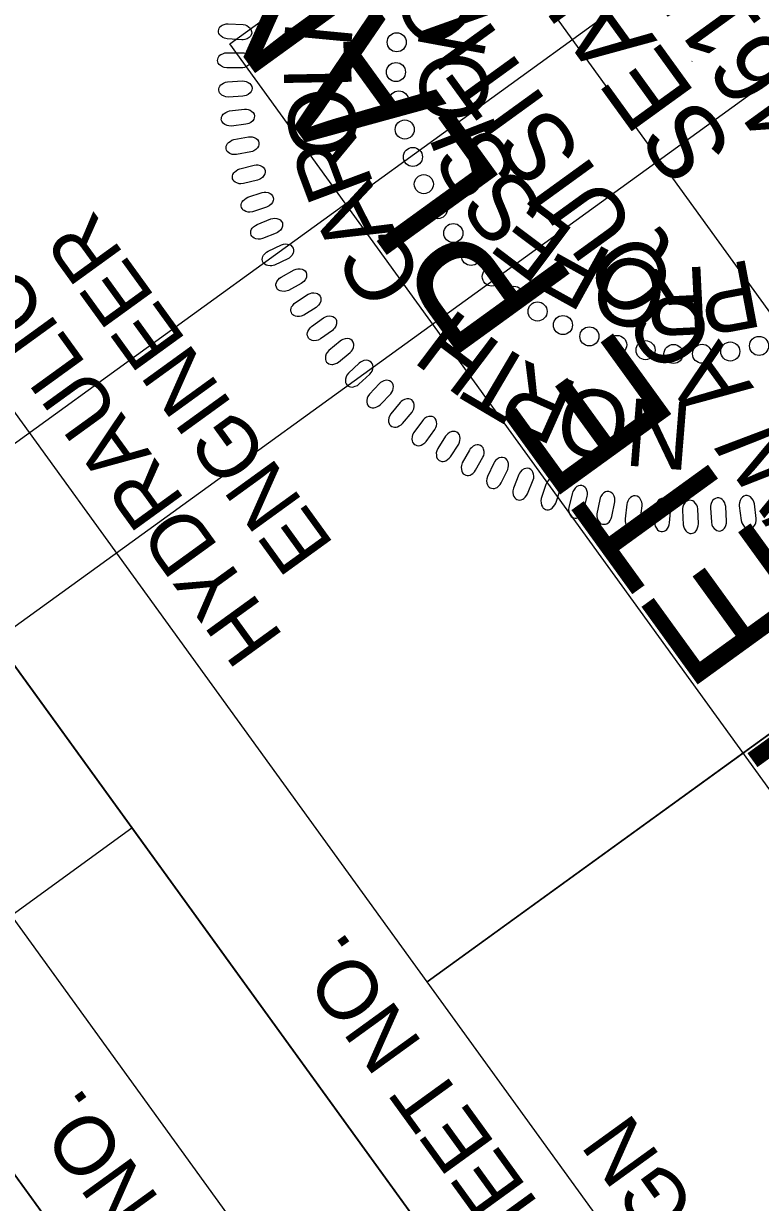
# Model space of a CAD drawing. Extents: x 474925 to 478950, y 494687 to 502905.
# Drawn here: x 475008.2 to 475070.1, y 502185.1 to 502284.1 of the extents above; entities that cross this region are included whole.
import ezdxf

# ---------------------------------------------------------------- set-up
doc = ezdxf.new("R2010")
doc.units = 0
for name, color, linetype in [('Sheet PE Seal Cell', 7, 'Continuous'), ('Sheet Plan CELL', 7, 'Continuous'), ('Sheet Plan Layout CELL', 7, 'Continuous'), ('Sheet Plot Border Inside CELL', 7, 'Continuous'), ('Sheet Sticker Incomplete CELL', 7, 'Continuous')]:
    doc.layers.add(name, color=color, linetype=linetype)

msp = doc.modelspace()

# ---------------------------------------------------------------- linework, layer by layer
at = {"layer": 'Sheet PE Seal Cell'}
msp.add_line((475064.349, 502280.924), (475064.387, 502280.952), dxfattribs=at)
for points in [[(475026.565, 502282.734), (475025.341, 502282.813), (475025.124, 502282.864), (475024.988, 502282.926), (475024.826, 502283.049), (475024.723, 502283.152), (475024.651, 502283.27), (475024.618, 502283.376), (475024.605, 502283.49), (475024.632, 502283.6), (475024.67, 502283.718), (475024.736, 502283.819), (475024.842, 502283.916), (475024.926, 502283.971), (475025.08, 502284.028), (475025.263, 502284.077), (475025.423, 502284.089), (475026.677, 502284.015), (475026.846, 502283.982), (475026.982, 502283.927), (475027.135, 502283.828), (475027.268, 502283.707), (475027.341, 502283.605), (475027.391, 502283.444), (475027.4, 502283.294), (475027.351, 502283.147), (475027.295, 502283.046), (475027.187, 502282.926), (475027.01, 502282.818), (475026.826, 502282.762), (475026.695, 502282.741)], [(475026.529, 502280.369), (475025.302, 502280.371), (475025.082, 502280.409), (475024.943, 502280.461), (475024.774, 502280.574), (475024.664, 502280.671), (475024.585, 502280.783), (475024.545, 502280.889), (475024.525, 502281.001), (475024.545, 502281.112), (475024.575, 502281.232), (475024.635, 502281.336), (475024.735, 502281.441), (475024.815, 502281.501), (475024.965, 502281.568), (475025.144, 502281.627), (475025.304, 502281.649), (475026.561, 502281.654), (475026.73, 502281.631), (475026.87, 502281.586), (475027.029, 502281.497), (475027.169, 502281.384), (475027.248, 502281.286), (475027.308, 502281.129), (475027.327, 502280.98), (475027.288, 502280.83), (475027.237, 502280.726), (475027.138, 502280.599), (475026.967, 502280.48), (475026.788, 502280.413), (475026.658, 502280.383)], [(475026.67, 502278.002), (475025.446, 502277.928), (475025.225, 502277.951), (475025.082, 502277.995), (475024.906, 502278.097), (475024.79, 502278.187), (475024.704, 502278.294), (475024.658, 502278.396), (475024.631, 502278.507), (475024.644, 502278.62), (475024.667, 502278.741), (475024.72, 502278.849), (475024.813, 502278.96), (475024.89, 502279.024), (475025.035, 502279.101), (475025.21, 502279.171), (475025.368, 502279.203), (475026.622, 502279.287), (475026.792, 502279.275), (475026.934, 502279.239), (475027.099, 502279.159), (475027.245, 502279.056), (475027.332, 502278.964), (475027.401, 502278.81), (475027.429, 502278.662), (475027.399, 502278.511), (475027.355, 502278.403), (475027.264, 502278.27), (475027.102, 502278.141), (475026.926, 502278.063), (475026.799, 502278.025)], [(475026.917, 502275.64), (475025.7, 502275.489), (475025.478, 502275.499), (475025.333, 502275.533), (475025.151, 502275.624), (475025.03, 502275.707), (475024.937, 502275.808), (475024.884, 502275.907), (475024.851, 502276.016), (475024.857, 502276.13), (475024.872, 502276.252), (475024.918, 502276.363), (475025.004, 502276.479), (475025.076, 502276.548), (475025.216, 502276.634), (475025.387, 502276.715), (475025.542, 502276.758), (475026.789, 502276.92), (475026.959, 502276.918), (475027.104, 502276.891), (475027.273, 502276.822), (475027.426, 502276.728), (475027.517, 502276.641), (475027.596, 502276.493), (475027.634, 502276.347), (475027.613, 502276.194), (475027.576, 502276.083), (475027.492, 502275.945), (475027.339, 502275.806), (475027.169, 502275.717), (475027.044, 502275.671)], [(475027.341, 502273.324), (475026.135, 502273.097), (475025.913, 502273.093), (475025.766, 502273.118), (475025.578, 502273.197), (475025.453, 502273.272), (475025.354, 502273.368), (475025.295, 502273.463), (475025.254, 502273.57), (475025.254, 502273.684), (475025.26, 502273.807), (475025.3, 502273.921), (475025.379, 502274.042), (475025.446, 502274.115), (475025.581, 502274.209), (475025.746, 502274.301), (475025.898, 502274.353), (475027.132, 502274.594), (475027.302, 502274.603), (475027.448, 502274.585), (475027.622, 502274.526), (475027.78, 502274.442), (475027.876, 502274.361), (475027.964, 502274.218), (475028.011, 502274.074), (475028, 502273.921), (475027.97, 502273.809), (475027.896, 502273.665), (475027.751, 502273.516), (475027.587, 502273.417), (475027.466, 502273.364)], [(475027.899, 502270.961), (475026.71, 502270.659), (475026.488, 502270.641), (475026.34, 502270.656), (475026.148, 502270.724), (475026.017, 502270.791), (475025.913, 502270.88), (475025.848, 502270.971), (475025.801, 502271.075), (475025.793, 502271.188), (475025.792, 502271.312), (475025.825, 502271.428), (475025.895, 502271.554), (475025.958, 502271.632), (475026.086, 502271.734), (475026.245, 502271.836), (475026.394, 502271.897), (475027.61, 502272.215), (475027.78, 502272.234), (475027.927, 502272.226), (475028.103, 502272.178), (475028.267, 502272.104), (475028.368, 502272.03), (475028.464, 502271.892), (475028.52, 502271.752), (475028.519, 502271.598), (475028.496, 502271.484), (475028.431, 502271.336), (475028.296, 502271.178), (475028.139, 502271.068), (475028.02, 502271.008)], [(475028.643, 502268.681), (475027.475, 502268.304), (475027.254, 502268.272), (475027.106, 502268.279), (475026.91, 502268.334), (475026.776, 502268.393), (475026.665, 502268.474), (475026.596, 502268.562), (475026.542, 502268.663), (475026.527, 502268.775), (475026.519, 502268.899), (475026.543, 502269.017), (475026.606, 502269.146), (475026.663, 502269.228), (475026.785, 502269.338), (475026.938, 502269.45), (475027.082, 502269.521), (475028.276, 502269.913), (475028.444, 502269.945), (475028.591, 502269.945), (475028.771, 502269.909), (475028.938, 502269.844), (475029.043, 502269.777), (475029.149, 502269.645), (475029.213, 502269.509), (475029.221, 502269.355), (475029.206, 502269.24), (475029.15, 502269.088), (475029.026, 502268.923), (475028.876, 502268.803), (475028.761, 502268.735)], [(475029.458, 502266.494), (475028.317, 502266.044), (475028.1, 502265.999), (475027.95, 502265.996), (475027.751, 502266.038), (475027.614, 502266.088), (475027.498, 502266.164), (475027.423, 502266.246), (475027.363, 502266.344), (475027.34, 502266.455), (475027.324, 502266.577), (475027.342, 502266.697), (475027.396, 502266.83), (475027.448, 502266.915), (475027.563, 502267.033), (475027.708, 502267.154), (475027.849, 502267.234), (475029.015, 502267.701), (475029.181, 502267.742), (475029.328, 502267.751), (475029.509, 502267.726), (475029.68, 502267.673), (475029.79, 502267.612), (475029.903, 502267.488), (475029.976, 502267.356), (475029.993, 502267.202), (475029.986, 502267.087), (475029.939, 502266.932), (475029.826, 502266.758), (475029.683, 502266.63), (475029.574, 502266.555)], [(475030.426, 502264.348), (475029.316, 502263.829), (475029.101, 502263.769), (475028.953, 502263.758), (475028.751, 502263.787), (475028.611, 502263.829), (475028.491, 502263.896), (475028.411, 502263.974), (475028.345, 502264.067), (475028.315, 502264.177), (475028.292, 502264.298), (475028.302, 502264.419), (475028.348, 502264.556), (475028.394, 502264.643), (475028.501, 502264.768), (475028.638, 502264.898), (475028.774, 502264.987), (475029.909, 502265.526), (475030.072, 502265.577), (475030.217, 502265.596), (475030.4, 502265.582), (475030.574, 502265.54), (475030.687, 502265.486), (475030.808, 502265.369), (475030.889, 502265.242), (475030.917, 502265.09), (475030.916, 502264.974), (475030.879, 502264.817), (475030.776, 502264.636), (475030.643, 502264.499), (475030.537, 502264.417)], [(475031.566, 502262.286), (475030.49, 502261.697), (475030.28, 502261.624), (475030.133, 502261.603), (475029.93, 502261.62), (475029.787, 502261.653), (475029.663, 502261.713), (475029.578, 502261.785), (475029.507, 502261.874), (475029.47, 502261.983), (475029.439, 502262.101), (475029.441, 502262.222), (475029.479, 502262.362), (475029.52, 502262.452), (475029.619, 502262.584), (475029.748, 502262.722), (475029.877, 502262.818), (475030.976, 502263.428), (475031.135, 502263.49), (475031.279, 502263.517), (475031.462, 502263.515), (475031.638, 502263.484), (475031.755, 502263.437), (475031.883, 502263.328), (475031.972, 502263.207), (475032.009, 502263.056), (475032.016, 502262.941), (475031.989, 502262.781), (475031.898, 502262.594), (475031.772, 502262.45), (475031.673, 502262.361)], [(475032.81, 502260.27), (475031.773, 502259.614), (475031.568, 502259.528), (475031.422, 502259.498), (475031.218, 502259.503), (475031.074, 502259.526), (475030.946, 502259.578), (475030.857, 502259.646), (475030.78, 502259.73), (475030.737, 502259.835), (475030.699, 502259.952), (475030.693, 502260.073), (475030.721, 502260.214), (475030.757, 502260.307), (475030.847, 502260.444), (475030.967, 502260.591), (475031.09, 502260.695), (475032.149, 502261.372), (475032.304, 502261.444), (475032.446, 502261.481), (475032.629, 502261.49), (475032.806, 502261.47), (475032.926, 502261.431), (475033.061, 502261.33), (475033.158, 502261.214), (475033.204, 502261.066), (475033.217, 502260.951), (475033.201, 502260.79), (475033.121, 502260.599), (475033.006, 502260.446), (475032.911, 502260.351)], [(475034.172, 502258.343), (475033.179, 502257.624), (475032.979, 502257.526), (475032.834, 502257.486), (475032.632, 502257.478), (475032.486, 502257.492), (475032.356, 502257.536), (475032.262, 502257.597), (475032.18, 502257.677), (475032.131, 502257.779), (475032.085, 502257.894), (475032.072, 502258.013), (475032.091, 502258.157), (475032.121, 502258.252), (475032.203, 502258.394), (475032.313, 502258.548), (475032.429, 502258.66), (475033.443, 502259.402), (475033.593, 502259.484), (475033.733, 502259.529), (475033.914, 502259.55), (475034.094, 502259.541), (475034.215, 502259.509), (475034.356, 502259.417), (475034.459, 502259.307), (475034.515, 502259.163), (475034.535, 502259.049), (475034.53, 502258.888), (475034.462, 502258.691), (475034.356, 502258.531), (475034.268, 502258.431)], [(475034.834, 502257.445), (475033.887, 502256.665), (475033.741, 502256.496), (475033.667, 502256.368), (475033.607, 502256.173), (475033.584, 502256.028), (475033.594, 502255.891), (475033.63, 502255.785), (475033.686, 502255.686), (475033.773, 502255.612), (475033.872, 502255.539), (475033.984, 502255.496), (475034.128, 502255.479), (475034.227, 502255.483), (475034.386, 502255.526), (475034.563, 502255.594), (475034.7, 502255.678), (475035.674, 502256.472), (475035.791, 502256.597), (475035.87, 502256.72), (475035.937, 502256.891), (475035.972, 502257.067), (475035.973, 502257.192), (475035.919, 502257.352), (475035.839, 502257.48), (475035.713, 502257.57), (475035.608, 502257.619), (475035.45, 502257.653), (475035.244, 502257.638), (475035.062, 502257.575), (475034.943, 502257.516)], [(475036.428, 502255.589), (475035.532, 502254.751), (475035.397, 502254.574), (475035.331, 502254.44), (475035.284, 502254.243), (475035.27, 502254.097), (475035.288, 502253.961), (475035.331, 502253.856), (475035.393, 502253.761), (475035.484, 502253.693), (475035.588, 502253.626), (475035.703, 502253.59), (475035.847, 502253.582), (475035.946, 502253.593), (475036.101, 502253.646), (475036.273, 502253.725), (475036.405, 502253.817), (475037.328, 502254.67), (475037.436, 502254.803), (475037.508, 502254.931), (475037.563, 502255.105), (475037.588, 502255.282), (475037.58, 502255.408), (475037.517, 502255.564), (475037.429, 502255.687), (475037.298, 502255.768), (475037.19, 502255.811), (475037.03, 502255.835), (475036.825, 502255.807), (475036.648, 502255.733), (475036.533, 502255.666)], [(475038.122, 502253.876), (475037.281, 502252.984), (475037.158, 502252.799), (475037.1, 502252.661), (475037.065, 502252.461), (475037.061, 502252.315), (475037.087, 502252.179), (475037.136, 502252.079), (475037.204, 502251.987), (475037.299, 502251.924), (475037.407, 502251.865), (475037.524, 502251.836), (475037.669, 502251.837), (475037.767, 502251.854), (475037.919, 502251.917), (475038.085, 502252.006), (475038.211, 502252.107), (475039.078, 502253.016), (475039.179, 502253.155), (475039.242, 502253.287), (475039.286, 502253.465), (475039.3, 502253.644), (475039.284, 502253.768), (475039.211, 502253.919), (475039.116, 502254.036), (475038.979, 502254.11), (475038.869, 502254.145), (475038.708, 502254.16), (475038.505, 502254.119), (475038.333, 502254.034), (475038.223, 502253.96)], [(475039.857, 502252.286), (475039.073, 502251.342), (475038.962, 502251.15), (475038.912, 502251.009), (475038.891, 502250.807), (475038.895, 502250.66), (475038.931, 502250.527), (475038.985, 502250.429), (475039.059, 502250.343), (475039.158, 502250.286), (475039.269, 502250.233), (475039.388, 502250.212), (475039.532, 502250.222), (475039.629, 502250.245), (475039.777, 502250.317), (475039.937, 502250.417), (475040.056, 502250.525), (475040.865, 502251.487), (475040.956, 502251.632), (475041.011, 502251.768), (475041.044, 502251.948), (475041.047, 502252.127), (475041.023, 502252.25), (475040.94, 502252.398), (475040.838, 502252.508), (475040.698, 502252.573), (475040.585, 502252.602), (475040.424, 502252.606), (475040.224, 502252.552), (475040.057, 502252.457), (475039.952, 502252.376)], [(475041.728, 502250.76), (475041.005, 502249.769), (475040.906, 502249.57), (475040.866, 502249.426), (475040.856, 502249.223), (475040.87, 502249.077), (475040.914, 502248.947), (475040.975, 502248.852), (475041.054, 502248.77), (475041.156, 502248.72), (475041.27, 502248.674), (475041.39, 502248.661), (475041.533, 502248.679), (475041.629, 502248.709), (475041.772, 502248.79), (475041.926, 502248.9), (475042.038, 502249.015), (475042.785, 502250.026), (475042.866, 502250.176), (475042.912, 502250.316), (475042.934, 502250.497), (475042.926, 502250.676), (475042.894, 502250.798), (475042.802, 502250.939), (475042.693, 502251.043), (475042.549, 502251.099), (475042.435, 502251.12), (475042.274, 502251.115), (475042.077, 502251.048), (475041.917, 502250.943), (475041.816, 502250.856)], [(475043.68, 502249.456), (475043.021, 502248.421), (475042.935, 502248.216), (475042.903, 502248.071), (475042.907, 502247.867), (475042.93, 502247.723), (475042.982, 502247.595), (475043.048, 502247.505), (475043.133, 502247.428), (475043.238, 502247.385), (475043.355, 502247.346), (475043.475, 502247.34), (475043.617, 502247.367), (475043.71, 502247.403), (475043.847, 502247.493), (475043.994, 502247.612), (475044.099, 502247.734), (475044.78, 502248.79), (475044.852, 502248.945), (475044.89, 502249.087), (475044.9, 502249.27), (475044.881, 502249.448), (475044.842, 502249.567), (475044.741, 502249.702), (475044.625, 502249.799), (475044.478, 502249.845), (475044.363, 502249.86), (475044.202, 502249.844), (475044.01, 502249.766), (475043.857, 502249.65), (475043.762, 502249.557)], [(475045.678, 502248.288), (475045.084, 502247.214), (475045.011, 502247.004), (475044.99, 502246.856), (475045.005, 502246.654), (475045.038, 502246.511), (475045.097, 502246.387), (475045.17, 502246.301), (475045.258, 502246.23), (475045.366, 502246.193), (475045.485, 502246.161), (475045.605, 502246.163), (475045.745, 502246.2), (475045.836, 502246.241), (475045.967, 502246.339), (475046.107, 502246.467), (475046.203, 502246.596), (475046.817, 502247.692), (475046.88, 502247.852), (475046.908, 502247.996), (475046.906, 502248.179), (475046.876, 502248.356), (475046.829, 502248.472), (475046.721, 502248.6), (475046.6, 502248.69), (475046.449, 502248.727), (475046.334, 502248.734), (475046.174, 502248.709), (475045.988, 502248.618), (475045.842, 502248.493), (475045.753, 502248.394)], [(475047.721, 502247.196), (475047.196, 502246.086), (475047.136, 502245.872), (475047.123, 502245.724), (475047.152, 502245.522), (475047.193, 502245.382), (475047.26, 502245.262), (475047.338, 502245.181), (475047.431, 502245.115), (475047.54, 502245.085), (475047.662, 502245.061), (475047.782, 502245.07), (475047.919, 502245.116), (475048.007, 502245.162), (475048.132, 502245.268), (475048.263, 502245.405), (475048.351, 502245.54), (475048.895, 502246.673), (475048.948, 502246.835), (475048.966, 502246.981), (475048.954, 502247.163), (475048.912, 502247.338), (475048.859, 502247.451), (475048.742, 502247.573), (475048.616, 502247.654), (475048.463, 502247.682), (475048.348, 502247.682), (475048.19, 502247.646), (475048.01, 502247.544), (475047.872, 502247.411), (475047.789, 502247.306)], [(475049.829, 502246.231), (475049.375, 502245.092), (475049.328, 502244.874), (475049.325, 502244.725), (475049.366, 502244.526), (475049.416, 502244.388), (475049.491, 502244.273), (475049.573, 502244.197), (475049.67, 502244.137), (475049.782, 502244.113), (475049.904, 502244.097), (475050.023, 502244.114), (475050.157, 502244.168), (475050.243, 502244.22), (475050.361, 502244.334), (475050.482, 502244.479), (475050.563, 502244.619), (475051.034, 502245.784), (475051.076, 502245.949), (475051.086, 502246.096), (475051.061, 502246.277), (475051.009, 502246.448), (475050.949, 502246.558), (475050.825, 502246.672), (475050.693, 502246.746), (475050.54, 502246.764), (475050.424, 502246.756), (475050.269, 502246.711), (475050.095, 502246.597), (475049.966, 502246.455), (475049.891, 502246.346)], [(475052.099, 502245.405), (475051.718, 502244.239), (475051.685, 502244.019), (475051.691, 502243.87), (475051.745, 502243.674), (475051.804, 502243.54), (475051.885, 502243.429), (475051.972, 502243.358), (475052.073, 502243.305), (475052.185, 502243.289), (475052.308, 502243.28), (475052.426, 502243.304), (475052.557, 502243.367), (475052.639, 502243.424), (475052.749, 502243.546), (475052.862, 502243.697), (475052.933, 502243.842), (475053.33, 502245.034), (475053.362, 502245.202), (475053.363, 502245.349), (475053.327, 502245.528), (475053.264, 502245.696), (475053.196, 502245.802), (475053.066, 502245.907), (475052.93, 502245.973), (475052.775, 502245.981), (475052.661, 502245.966), (475052.508, 502245.912), (475052.342, 502245.787), (475052.222, 502245.638), (475052.154, 502245.524)], [(475054.327, 502244.697), (475054.02, 502243.509), (475054.001, 502243.288), (475054.016, 502243.139), (475054.083, 502242.947), (475054.149, 502242.816), (475054.237, 502242.711), (475054.329, 502242.647), (475054.433, 502242.599), (475054.547, 502242.59), (475054.67, 502242.589), (475054.786, 502242.62), (475054.912, 502242.691), (475054.99, 502242.753), (475055.093, 502242.882), (475055.196, 502243.04), (475055.258, 502243.189), (475055.58, 502244.403), (475055.6, 502244.573), (475055.592, 502244.72), (475055.545, 502244.896), (475055.471, 502245.06), (475055.397, 502245.162), (475055.26, 502245.259), (475055.12, 502245.315), (475054.966, 502245.314), (475054.852, 502245.292), (475054.704, 502245.228), (475054.546, 502245.093), (475054.436, 502244.936), (475054.374, 502244.818)], [(475056.622, 502244.151), (475056.39, 502242.947), (475056.385, 502242.724), (475056.41, 502242.577), (475056.488, 502242.389), (475056.562, 502242.264), (475056.657, 502242.164), (475056.753, 502242.105), (475056.859, 502242.064), (475056.973, 502242.062), (475057.096, 502242.069), (475057.21, 502242.108), (475057.332, 502242.186), (475057.406, 502242.253), (475057.5, 502242.387), (475057.593, 502242.552), (475057.645, 502242.704), (475057.89, 502243.937), (475057.9, 502244.108), (475057.882, 502244.253), (475057.825, 502244.427), (475057.741, 502244.586), (475057.661, 502244.683), (475057.518, 502244.771), (475057.374, 502244.819), (475057.22, 502244.807), (475057.108, 502244.779), (475056.964, 502244.705), (475056.815, 502244.561), (475056.715, 502244.397), (475056.661, 502244.276)], [(475058.9, 502243.749), (475058.744, 502242.532), (475058.754, 502242.31), (475058.787, 502242.165), (475058.877, 502241.982), (475058.959, 502241.861), (475059.061, 502241.767), (475059.159, 502241.715), (475059.268, 502241.681), (475059.381, 502241.686), (475059.504, 502241.701), (475059.615, 502241.746), (475059.732, 502241.832), (475059.802, 502241.904), (475059.888, 502242.043), (475059.97, 502242.214), (475060.013, 502242.369), (475060.18, 502243.615), (475060.179, 502243.785), (475060.152, 502243.93), (475060.083, 502244.1), (475059.99, 502244.252), (475059.904, 502244.344), (475059.756, 502244.423), (475059.61, 502244.462), (475059.457, 502244.441), (475059.347, 502244.405), (475059.208, 502244.323), (475059.067, 502244.169), (475058.978, 502244), (475058.932, 502243.876)], [(475068.342, 502243.602), (475068.493, 502242.384), (475068.557, 502242.172), (475068.626, 502242.039), (475068.758, 502241.885), (475068.869, 502241.788), (475068.989, 502241.723), (475069.098, 502241.696), (475069.212, 502241.69), (475069.321, 502241.724), (475069.436, 502241.768), (475069.532, 502241.84), (475069.624, 502241.952), (475069.673, 502242.039), (475069.722, 502242.196), (475069.759, 502242.381), (475069.761, 502242.543), (475069.614, 502243.79), (475069.571, 502243.956), (475069.509, 502244.088), (475069.4, 502244.236), (475069.272, 502244.361), (475069.165, 502244.428), (475069.002, 502244.468), (475068.851, 502244.469), (475068.708, 502244.411), (475068.61, 502244.349), (475068.496, 502244.234), (475068.399, 502244.052), (475068.354, 502243.865), (475068.34, 502243.733)], [(475061.294, 502243.49), (475061.214, 502242.266), (475061.238, 502242.044), (475061.281, 502241.902), (475061.382, 502241.725), (475061.471, 502241.609), (475061.578, 502241.523), (475061.68, 502241.476), (475061.791, 502241.449), (475061.904, 502241.461), (475062.025, 502241.484), (475062.134, 502241.536), (475062.244, 502241.629), (475062.309, 502241.705), (475062.386, 502241.85), (475062.458, 502242.026), (475062.49, 502242.183), (475062.579, 502243.437), (475062.568, 502243.607), (475062.532, 502243.749), (475062.452, 502243.915), (475062.35, 502244.061), (475062.257, 502244.147), (475062.105, 502244.217), (475061.957, 502244.246), (475061.805, 502244.216), (475061.698, 502244.173), (475061.564, 502244.082), (475061.434, 502243.921), (475061.355, 502243.746), (475061.317, 502243.618)], [(475063.567, 502243.253), (475063.632, 502242.029), (475063.681, 502241.811), (475063.74, 502241.675), (475063.861, 502241.511), (475063.964, 502241.407), (475064.08, 502241.334), (475064.186, 502241.299), (475064.3, 502241.285), (475064.411, 502241.311), (475064.529, 502241.348), (475064.63, 502241.412), (475064.729, 502241.517), (475064.785, 502241.6), (475064.844, 502241.753), (475064.894, 502241.936), (475064.908, 502242.096), (475064.849, 502243.351), (475064.818, 502243.52), (475064.765, 502243.656), (475064.667, 502243.811), (475064.548, 502243.944), (475064.446, 502244.019), (475064.287, 502244.07), (475064.137, 502244.082), (475063.989, 502244.035), (475063.888, 502243.979), (475063.766, 502243.873), (475063.656, 502243.698), (475063.598, 502243.515), (475063.575, 502243.384)], [(475065.917, 502243.456), (475065.992, 502242.232), (475066.043, 502242.015), (475066.103, 502241.879), (475066.225, 502241.716), (475066.329, 502241.613), (475066.446, 502241.54), (475066.553, 502241.507), (475066.666, 502241.493), (475066.777, 502241.52), (475066.894, 502241.558), (475066.995, 502241.623), (475067.093, 502241.729), (475067.149, 502241.812), (475067.207, 502241.967), (475067.255, 502242.149), (475067.268, 502242.309), (475067.199, 502243.564), (475067.166, 502243.732), (475067.113, 502243.869), (475067.014, 502244.022), (475066.893, 502244.155), (475066.792, 502244.229), (475066.631, 502244.279), (475066.48, 502244.29), (475066.334, 502244.241), (475066.232, 502244.185), (475066.111, 502244.077), (475066.003, 502243.901), (475065.946, 502243.718), (475065.924, 502243.586)]]:
    msp.add_lwpolyline(points, close=True, dxfattribs=at)
for centre in [(475039.574, 502282.528), (475039.515, 502280.028), (475039.76, 502277.65), (475040.251, 502275.205), (475040.936, 502272.899), (475041.852, 502270.613), (475043.027, 502268.515), (475044.33, 502266.509), (475045.818, 502264.588), (475047.565, 502262.854), (475049.417, 502261.246), (475051.402, 502259.93), (475053.536, 502258.791), (475055.751, 502257.838), (475058.088, 502257.121), (475060.471, 502256.683), (475067.583, 502256.571), (475069.997, 502257.04), (475062.815, 502256.365), (475065.214, 502256.38)]:
    msp.add_circle(centre, 0.801, dxfattribs=at)
at = {"layer": 'Sheet Plan CELL'}
for p, q in [((475090.699, 502115.3), (474973.361, 502277.308)), ((475090.699, 502115.3), (474973.361, 502277.308)), ((475080.552, 502107.936), (474963.237, 502269.977)), ((475042.137, 502203.66), (475133.22, 502269.627)), ((474997.123, 502201.886), (475017.343, 502216.589))]:
    msp.add_line(p, q, dxfattribs=at)
for points in [[(474953.05, 502262.647), (475832.788, 501047.669), (476683.252, 501663.47), (475803.528, 502878.428)], [(475042.137, 502203.66), (474983.486, 502284.639), (475074.61, 502350.635), (475133.268, 502269.646)], [(475070.379, 502100.586), (474953.05, 502262.647), (474973.361, 502277.308), (475090.699, 502115.3)], [(475100.814, 502122.623), (475042.137, 502203.66), (475133.268, 502269.646), (475191.917, 502188.605)]]:
    msp.add_lwpolyline(points, close=True, dxfattribs=at)
at = {"layer": 'Sheet Plan Layout CELL'}
msp.add_lwpolyline([(475297.285, 502147.842), (475156.955, 502341.646), (474985.643, 502217.634), (475125.987, 502023.809)], close=True, dxfattribs=at)
at = {"layer": 'Sheet Plot Border Inside CELL'}
msp.add_lwpolyline([(476807.904, 501495.6), (475830.83, 502844.985), (474976.319, 502226.269), (475953.391, 500876.866)], close=True, dxfattribs=at)
at = {"layer": 'Sheet Sticker Incomplete CELL'}
msp.add_lwpolyline([(475130.803, 502177.117), (475111.769, 502163.335), (475025.557, 502282.4), (475044.591, 502296.182)], close=True, dxfattribs=at)

# ---------------------------------------------------------------- texts
at = {"layer": 'Sheet PE Seal Cell'}
for s, height, rotation, p in [('46155', 6.2363, 125.88878, (475075.939, 502276.488)), ('SEAL', 6.2363, 125.88878, (475068.018, 502273.652)), ('N', 5.669, 79.55767, (475046.812, 502280.965)), ('I', 5.669, 84.55896, (475035.722, 502281.858)), ('L', 5.669, 91.04831, (475035.8, 502278.59)), ('O', 5.669, 95.43726, (475047.474, 502276.121)), ('O', 5.669, 97.53767, (475036.526, 502273.272)), ('I', 5.669, 111.31686, (475048.217, 502274.803)), ('R', 5.669, 110.51638, (475037.729, 502270.495)), ('S', 5.669, 119.25665, (475049.934, 502271.354)), ('A', 5.669, 117.00574, (475039.553, 502266.622)), ('S', 5.669, 127.19645, (475052.281, 502268.286)), ('E', 5.669, 143.07604, (475054.681, 502266.608)), ('C', 5.669, 123.4951, (475042.068, 502262.794)), ('F', 5.669, 151.01584, (475057.915, 502264.764)), ('O', 5.669, 166.89544, (475062.626, 502263.61)), ('P', 5.669, 190.71483, (475069.405, 502264.321)), ('R', 5.669, 182.77503, (475065.693, 502263.715)), ('H', 5.669, 142.96317, (475048.581, 502257.01)), ('T', 5.669, 149.45252, (475051.588, 502255.262)), ('R', 5.669, 155.94188, (475055.031, 502253.778)), ('O', 5.669, 168.92059, (475059.522, 502252.74)), ('N', 5.669, 175.40995, (475064.526, 502252.231))]:
    msp.add_text(s, height=height, rotation=rotation, dxfattribs=at).set_placement(p)
at = {"layer": 'Sheet Plan CELL'}
for s, p in [('ENGINEER', (475034.406, 502240.318)), ('HYDRAULICS', (475030.164, 502232.6)), ('R/W SHEET NO.', (475064.712, 502166.856)), ('PROJECT REFERENCE NO.', (475064.426, 502123.685)), ('ROADWAY DESIGN', (475095.363, 502142.598)), ('ENGINEER', (475093.265, 502158.347))]:
    msp.add_text(s, height=5.0001, rotation=125.90742, dxfattribs=at).set_placement(p)
at = {"layer": 'Sheet Sticker Incomplete CELL'}
for s, height, p in [('INCOMPLETE PLANS', 11.52, (475116.078, 502177.504)), ('DO NOT USE FOR R/W ACQUISITION', 5.76, (475119.801, 502184.213))]:
    msp.add_text(s, height=height, rotation=125.90742, dxfattribs=at).set_placement(p)

doc.saveas('drawing.dxf')
